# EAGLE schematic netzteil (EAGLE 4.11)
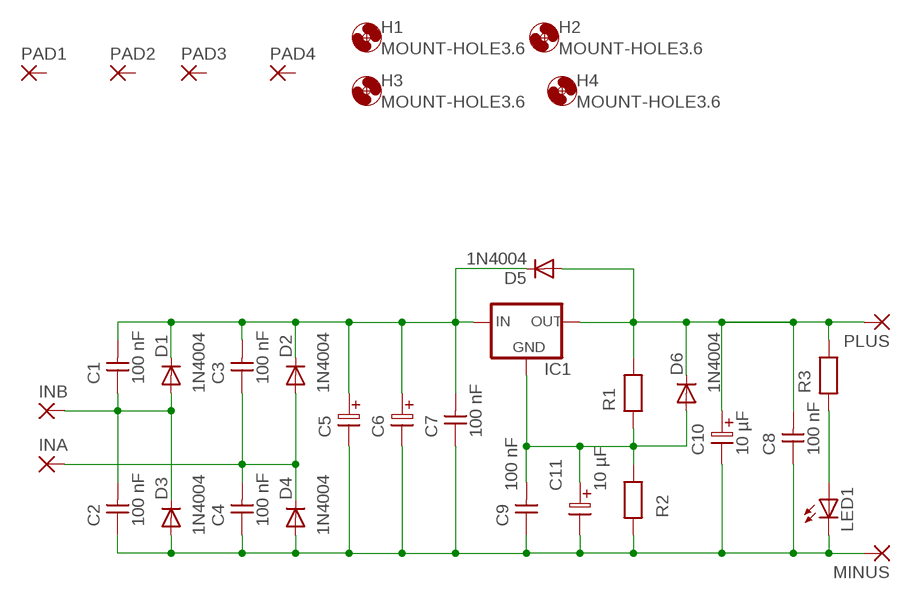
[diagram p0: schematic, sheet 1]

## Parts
C1  100 nF  CAPNP-5  [C-5]
C2  100 nF  CAPNP-5  [C-5]
C3  100 nF  CAPNP-5  [C-5]
C4  100 nF  CAPNP-5  [C-5]
C5  ELC-5L  [ES-5L]
C6  ELC-5L  [ES-5L]
C7  100 nF  CAPNP-5  [C-5]
C8  100 nF  CAPNP-5  [C-5]
C9  100 nF  CAPNP-5  [C-5]
C10  10 µF  ELC-2,5L  [ES-2,5L]
C11  10 µF  ELC-2,5L  [ES-2,5L]
D1  1N4004  [DO41-10]
D2  1N4004  [DO41-10]
D3  1N4004  [DO41-10]
D4  1N4004  [DO41-10]
D5  1N4004  [DO41-10]
D6  1N4004  [DO41-10]
H1  MOUNT-HOLE3.6  [3,6]
H2  MOUNT-HOLE3.6  [3,6]
H3  MOUNT-HOLE3.6  [3,6]
H4  MOUNT-HOLE3.6  [3,6]
IC1  78XXL  [78XXL]
INA  2,54/0,8  [2,54/0,8]
INB  2,54/0,8  [2,54/0,8]
LED1  LED5MM  [LED5MM]
MINUS  2,54/0,8  [2,54/0,8]
PAD1  2,54/0,8  [2,54/0,8]
PAD2  2,54/0,8  [2,54/0,8]
PAD3  2,54/0,8  [2,54/0,8]
PAD4  2,54/0,8  [2,54/0,8]
PLUS  2,54/0,8  [2,54/0,8]
R1  RESEU-10  [R-10]
R2  RESEU-10  [R-10]
R3  RESEU-10  [R-10]

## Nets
GND: C2.1 C4.1 C5.2 C6.2 C7.1 C8.1 C9.1 C10.2 C11.2 D3.A D4.A LED1.K(C) MINUS.1(P) R2.1
N$1: C1.2 C3.2 C5.1 C6.1 C7.2 D1.C D2.C D5.C IC1.IN
N$2: C8.2 C10.1 D5.A D6.C IC1.OUT PLUS.1(P) R1.2 R3.2
N$3: C9.2 C11.1 D6.A IC1.GND R1.1 R2.2
N$8: LED1.A R3.1
N$15: C3.1 C4.2 D2.A D4.C INA.1(P)
N$16: C1.1 C2.2 D1.A D3.C INB.1(P)
Unconnected: PAD1.1(P) PAD2.1(P) PAD3.1(P) PAD4.1(P)

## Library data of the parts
C1-C4 C7-C9 = discrete:CAPNP-5
C5 C6 = discrete:ELC-5L
C10 C11 = discrete:ELC-2,5L
D1-D6 = diode:1N4004: DIODE
H1-H4 = holes:MOUNT-HOLE: MOUNTING HOLE with drill center marker
IC1 = v-reg:78XXL: VOLTAGE REGULATOR
INA INB MINUS PAD1-PAD4 PLUS = wirepad:2,54/0,8: THROUGH-HOLE PAD
LED1 = led:LED: LED
R1-R3 = discrete:RESEU-10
